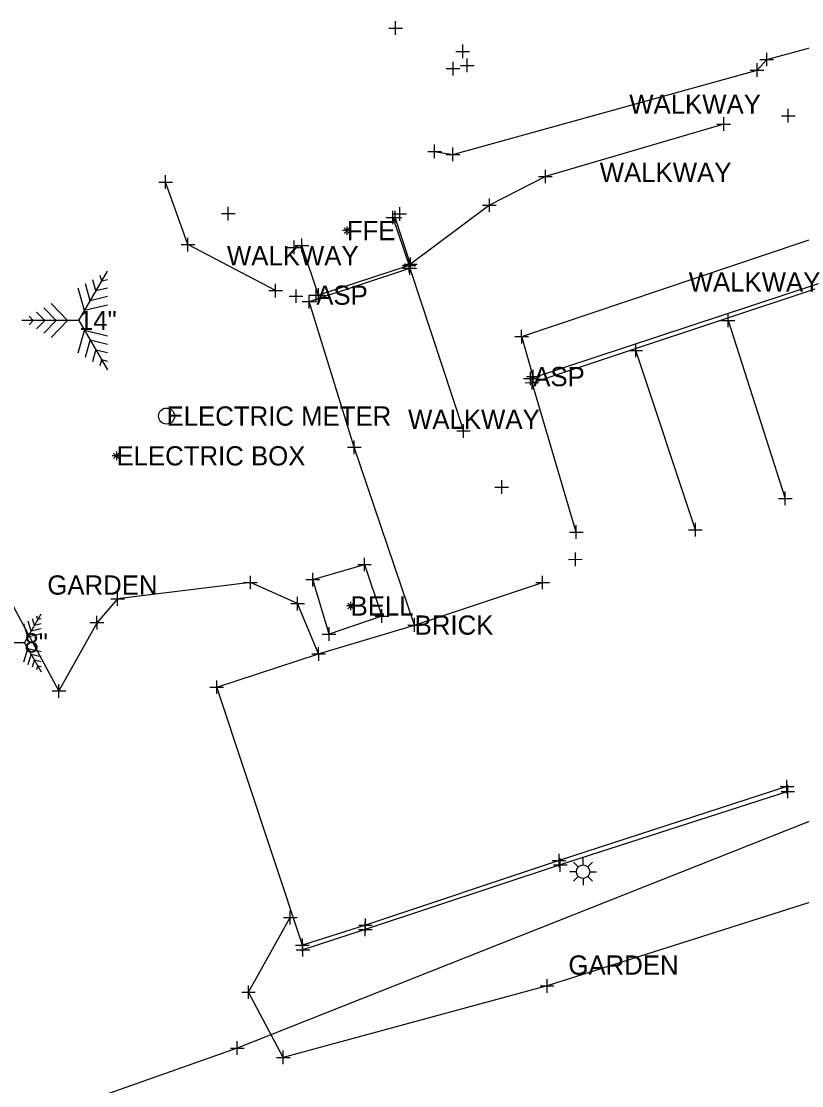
# Model space of a CAD drawing. Extents: x 1729655 to 1739338, y 463812 to 469501.
# Drawn here: x 1734912.1 to 1734985, y 466865.3 to 466964.8 of the extents above; entities that cross this region are included whole.
import ezdxf

# ---------------------------------------------------------------- set-up
doc = ezdxf.new("R2010")
doc.units = 0
for name, color, linetype in [('S_Bridge_Column_Round', 7, 'Continuous'), ('S_Bridge_Deck', 7, 'Continuous'), ('S_Bridge_Parapet', 7, 'Continuous'), ('S_Buildings_Steps', 7, 'Continuous'), ('S_Drainage_Invert_Culvert', 7, 'Continuous'), ('S_Fencing_ChainLink', 7, 'Continuous'), ('S_Fencing_Other', 7, 'Continuous'), ('S_Ground_SpotElevation', 7, 'Continuous'), ('S_Property_Garden', 7, 'Continuous'), ('S_Roadway_Drive_Gravel', 7, 'Continuous'), ('S_Roadway_Sidewalks', 7, 'Continuous'), ('S_Terrain_High_Points', 7, 'Continuous'), ('S_Utilities_Pole_StreetLight', 7, 'Continuous'), ('S_Utilities_UG_Sanitary_MH', 7, 'Continuous')]:
    doc.layers.add(name, color=color, linetype=linetype)

msp = doc.modelspace()

# ---------------------------------------------------------------- linework, layer by layer
at = {"layer": 'S_Bridge_Column_Round'}
for p, q in [((1734946.419, 466964.211), (1734947.691, 466964.213)), ((1734947.056, 466963.576), (1734947.054, 466964.848)), ((1734947.055, 466964.212), (1734947.055, 466964.212)), ((1734953.322, 466961.394), (1734953.32, 466962.666)), ((1734952.685, 466962.029), (1734953.957, 466962.031)), ((1734953.321, 466962.03), (1734953.321, 466962.03)), ((1734953.745, 466960.092), (1734953.743, 466961.364)), ((1734981.087, 466961.276), (1734982.359, 466961.278)), ((1734981.087, 466961.276), (1734982.359, 466961.278)), ((1734981.724, 466960.641), (1734981.722, 466961.913)), ((1734981.724, 466960.641), (1734981.722, 466961.913)), ((1734981.723, 466961.277), (1734981.723, 466961.277)), ((1734981.723, 466961.277), (1734981.723, 466961.277)), ((1734951.79, 466960.426), (1734953.062, 466960.428)), ((1734952.427, 466959.791), (1734952.425, 466961.063)), ((1734952.426, 466960.427), (1734952.426, 466960.427)), ((1734953.108, 466960.727), (1734954.38, 466960.729)), ((1734953.744, 466960.728), (1734953.744, 466960.728)), ((1734980.19, 466960.285), (1734981.462, 466960.287)), ((1734980.827, 466959.65), (1734980.825, 466960.922)), ((1734980.826, 466960.286), (1734980.826, 466960.286)), ((1734983.745, 466955.388), (1734983.743, 466956.66)), ((1734977.079, 466955.237), (1734978.351, 466955.239)), ((1734977.716, 466954.602), (1734977.714, 466955.874)), ((1734977.715, 466955.238), (1734977.715, 466955.238)), ((1734983.108, 466956.023), (1734984.38, 466956.025)), ((1734983.744, 466956.024), (1734983.744, 466956.024)), ((1734950.695, 466952.046), (1734950.693, 466953.318)), ((1734950.695, 466952.046), (1734950.693, 466953.318)), ((1734950.058, 466952.681), (1734951.33, 466952.683)), ((1734950.058, 466952.681), (1734951.33, 466952.683)), ((1734950.694, 466952.682), (1734950.694, 466952.682)), ((1734950.694, 466952.682), (1734950.694, 466952.682)), ((1734951.77, 466952.4), (1734953.042, 466952.402)), ((1734952.407, 466951.765), (1734952.405, 466953.037)), ((1734952.406, 466952.401), (1734952.406, 466952.401)), ((1734925.557, 466949.184), (1734925.555, 466950.456)), ((1734960.407, 466950.337), (1734961.679, 466950.339)), ((1734961.044, 466949.702), (1734961.042, 466950.974)), ((1734961.043, 466950.338), (1734961.043, 466950.338)), ((1734924.92, 466949.819), (1734926.192, 466949.821)), ((1734925.556, 466949.82), (1734925.556, 466949.82)), ((1734955.822, 466947.021), (1734955.82, 466948.293)), ((1734931.419, 466946.236), (1734931.417, 466947.508)), ((1734947.449, 466946.201), (1734947.447, 466947.473)), ((1734955.185, 466947.656), (1734956.457, 466947.658)), ((1734955.821, 466947.657), (1734955.821, 466947.657)), ((1734930.782, 466946.871), (1734932.054, 466946.873)), ((1734931.418, 466946.872), (1734931.418, 466946.872)), ((1734946.161, 466946.504), (1734947.433, 466946.506)), ((1734946.367, 466946.49), (1734947.639, 466946.492)), ((1734946.798, 466945.869), (1734946.796, 466947.141)), ((1734946.797, 466946.505), (1734946.797, 466946.505)), ((1734946.812, 466946.836), (1734948.084, 466946.838)), ((1734947.004, 466945.855), (1734947.002, 466947.127)), ((1734947.003, 466946.491), (1734947.003, 466946.491)), ((1734947.448, 466946.837), (1734947.448, 466946.837)), ((1734927.648, 466943.332), (1734927.646, 466944.604)), ((1734937.57, 466943.076), (1734937.568, 466944.348)), ((1734938.299, 466943.266), (1734938.297, 466944.538)), ((1734927.011, 466943.967), (1734928.283, 466943.969)), ((1734927.647, 466943.968), (1734927.647, 466943.968)), ((1734936.933, 466943.711), (1734938.205, 466943.713)), ((1734937.569, 466943.712), (1734937.569, 466943.712)), ((1734937.662, 466943.901), (1734938.934, 466943.903)), ((1734938.298, 466943.902), (1734938.298, 466943.902)), ((1734948.306, 466941.379), (1734948.304, 466942.651)), ((1734948.371, 466941.135), (1734948.369, 466942.407)), ((1734948.442, 466941.495), (1734948.44, 466942.767)), ((1734947.669, 466942.014), (1734948.941, 466942.016)), ((1734947.734, 466941.77), (1734949.006, 466941.772)), ((1734947.805, 466942.13), (1734949.077, 466942.132)), ((1734948.305, 466942.015), (1734948.305, 466942.015)), ((1734948.37, 466941.771), (1734948.37, 466941.771)), ((1734948.441, 466942.131), (1734948.441, 466942.131)), ((1734935.84, 466939.036), (1734935.838, 466940.308)), ((1734935.203, 466939.671), (1734936.475, 466939.673)), ((1734935.839, 466939.672), (1734935.839, 466939.672)), ((1734937.75, 466938.519), (1734937.748, 466939.791)), ((1734938.967, 466938.007), (1734938.965, 466939.279)), ((1734939.002, 466939.246), (1734940.274, 466939.248)), ((1734939.002, 466939.246), (1734940.274, 466939.248)), ((1734939.222, 466939.249), (1734940.494, 466939.251)), ((1734939.639, 466938.611), (1734939.637, 466939.883)), ((1734939.639, 466938.611), (1734939.637, 466939.883)), ((1734939.638, 466939.247), (1734939.638, 466939.247)), ((1734939.638, 466939.247), (1734939.638, 466939.247)), ((1734939.859, 466938.614), (1734939.857, 466939.886)), ((1734939.858, 466939.25), (1734939.858, 466939.25)), ((1734937.113, 466939.154), (1734938.385, 466939.156)), ((1734937.749, 466939.155), (1734937.749, 466939.155)), ((1734938.33, 466938.642), (1734939.602, 466938.644)), ((1734938.966, 466938.643), (1734938.966, 466938.643)), ((1734978.117, 466936.252), (1734978.115, 466937.524)), ((1734977.48, 466936.887), (1734978.752, 466936.889)), ((1734978.116, 466936.888), (1734978.116, 466936.888)), ((1734958.194, 466935.373), (1734959.466, 466935.375)), ((1734958.831, 466934.738), (1734958.829, 466936.01)), ((1734958.83, 466935.374), (1734958.83, 466935.374)), ((1734969.484, 466933.438), (1734969.482, 466934.71)), ((1734968.847, 466934.073), (1734970.119, 466934.075)), ((1734969.483, 466934.074), (1734969.483, 466934.074)), ((1734959.911, 466930.999), (1734959.909, 466932.271)), ((1734959.007, 466931.457), (1734960.279, 466931.459)), ((1734959.274, 466931.634), (1734960.546, 466931.636)), ((1734959.644, 466930.822), (1734959.642, 466932.094)), ((1734959.643, 466931.458), (1734959.643, 466931.458)), ((1734959.799, 466930.43), (1734959.797, 466931.702)), ((1734959.91, 466931.635), (1734959.91, 466931.635)), ((1734959.162, 466931.065), (1734960.434, 466931.067)), ((1734959.798, 466931.066), (1734959.798, 466931.066)), ((1734952.76, 466926.551), (1734954.032, 466926.553)), ((1734953.397, 466925.916), (1734953.395, 466927.188)), ((1734953.396, 466926.552), (1734953.396, 466926.552)), ((1734943.193, 466924.389), (1734943.191, 466925.661)), ((1734942.556, 466925.024), (1734943.828, 466925.026)), ((1734943.192, 466925.025), (1734943.192, 466925.025)), ((1734956.963, 466920.673), (1734956.961, 466921.945)), ((1734956.326, 466921.308), (1734957.598, 466921.31)), ((1734956.962, 466921.309), (1734956.962, 466921.309)), ((1734983.462, 466919.608), (1734983.46, 466920.88)), ((1734982.825, 466920.243), (1734984.097, 466920.245)), ((1734983.461, 466920.244), (1734983.461, 466920.244)), ((1734963.929, 466916.464), (1734963.927, 466917.736)), ((1734963.929, 466916.464), (1734963.927, 466917.736)), ((1734975.063, 466916.68), (1734975.061, 466917.952)), ((1734963.292, 466917.099), (1734964.564, 466917.101)), ((1734963.292, 466917.099), (1734964.564, 466917.101)), ((1734963.928, 466917.1), (1734963.928, 466917.1)), ((1734963.928, 466917.1), (1734963.928, 466917.1)), ((1734974.426, 466917.315), (1734975.698, 466917.317)), ((1734975.062, 466917.316), (1734975.062, 466917.316)), ((1734944.144, 466913.432), (1734944.142, 466914.704)), ((1734963.218, 466914.551), (1734964.49, 466914.553)), ((1734963.855, 466913.916), (1734963.853, 466915.188)), ((1734963.854, 466914.552), (1734963.854, 466914.552)), ((1734943.507, 466914.067), (1734944.779, 466914.069)), ((1734944.143, 466914.068), (1734944.143, 466914.068)), ((1734932.85, 466912.387), (1734934.122, 466912.389)), ((1734933.487, 466911.752), (1734933.485, 466913.024)), ((1734933.486, 466912.388), (1734933.486, 466912.388)), ((1734938.669, 466912.662), (1734939.941, 466912.664)), ((1734939.306, 466912.027), (1734939.304, 466913.299)), ((1734939.305, 466912.663), (1734939.305, 466912.663)), ((1734960.147, 466912.384), (1734961.419, 466912.386)), ((1734960.784, 466911.749), (1734960.782, 466913.021)), ((1734960.783, 466912.385), (1734960.783, 466912.385)), ((1734921.074, 466910.214), (1734921.072, 466911.486)), ((1734920.437, 466910.849), (1734921.709, 466910.851)), ((1734921.073, 466910.85), (1734921.073, 466910.85)), ((1734937.254, 466910.408), (1734938.526, 466910.41)), ((1734937.891, 466909.773), (1734937.889, 466911.045)), ((1734937.89, 466910.409), (1734937.89, 466910.409)), ((1734945.77, 466908.615), (1734945.768, 466909.887)), ((1734918.514, 466908.642), (1734919.786, 466908.644)), ((1734919.151, 466908.007), (1734919.149, 466909.279)), ((1734919.15, 466908.643), (1734919.15, 466908.643)), ((1734945.133, 466909.25), (1734946.405, 466909.252)), ((1734945.769, 466909.251), (1734945.769, 466909.251)), ((1734948.193, 466908.405), (1734949.465, 466908.407)), ((1734948.193, 466908.405), (1734949.465, 466908.407)), ((1734948.83, 466907.77), (1734948.828, 466909.042)), ((1734948.83, 466907.77), (1734948.828, 466909.042)), ((1734948.829, 466908.406), (1734948.829, 466908.406)), ((1734948.829, 466908.406), (1734948.829, 466908.406)), ((1734940.2, 466907.56), (1734941.472, 466907.562)), ((1734940.837, 466906.925), (1734940.835, 466908.197)), ((1734940.836, 466907.561), (1734940.836, 466907.561)), ((1734939.225, 466905.707), (1734940.497, 466905.709)), ((1734939.225, 466905.707), (1734940.497, 466905.709)), ((1734939.862, 466905.072), (1734939.86, 466906.344)), ((1734939.862, 466905.072), (1734939.86, 466906.344)), ((1734939.861, 466905.708), (1734939.861, 466905.708)), ((1734939.861, 466905.708), (1734939.861, 466905.708)), ((1734915.597, 466901.61), (1734915.595, 466902.882)), ((1734929.704, 466902.602), (1734930.976, 466902.604)), ((1734930.341, 466901.967), (1734930.339, 466903.239)), ((1734930.34, 466902.603), (1734930.34, 466902.603)), ((1734914.96, 466902.245), (1734916.232, 466902.247)), ((1734915.596, 466902.246), (1734915.596, 466902.246)), ((1734983.619, 466892.677), (1734983.617, 466893.949)), ((1734983.703, 466892.216), (1734983.701, 466893.488)), ((1734982.982, 466893.312), (1734984.254, 466893.314)), ((1734983.066, 466892.851), (1734984.338, 466892.853)), ((1734983.618, 466893.313), (1734983.618, 466893.313)), ((1734983.702, 466892.852), (1734983.702, 466892.852)), ((1734962.326, 466885.765), (1734962.324, 466887.037)), ((1734962.436, 466885.344), (1734962.434, 466886.616)), ((1734961.689, 466886.4), (1734962.961, 466886.402)), ((1734961.799, 466885.979), (1734963.071, 466885.981)), ((1734962.325, 466886.401), (1734962.325, 466886.401)), ((1734962.435, 466885.98), (1734962.435, 466885.98)), ((1734937.206, 466880.424), (1734937.204, 466881.696)), ((1734936.569, 466881.059), (1734937.841, 466881.061)), ((1734937.205, 466881.06), (1734937.205, 466881.06)), ((1734944.219, 466879.324), (1734944.217, 466880.596)), ((1734944.241, 466879.707), (1734944.239, 466880.979)), ((1734943.582, 466879.959), (1734944.854, 466879.961)), ((1734943.604, 466880.342), (1734944.876, 466880.344)), ((1734944.218, 466879.96), (1734944.218, 466879.96)), ((1734944.24, 466880.343), (1734944.24, 466880.343)), ((1734938.343, 466877.845), (1734938.341, 466879.117)), ((1734938.39, 466877.416), (1734938.388, 466878.688)), ((1734937.706, 466878.48), (1734938.978, 466878.482)), ((1734937.753, 466878.051), (1734939.025, 466878.053)), ((1734938.342, 466878.481), (1734938.342, 466878.481)), ((1734938.389, 466878.052), (1734938.389, 466878.052)), ((1734933.305, 466873.454), (1734933.303, 466874.726)), ((1734960.572, 466874.674), (1734961.844, 466874.676)), ((1734961.209, 466874.039), (1734961.207, 466875.311)), ((1734961.208, 466874.675), (1734961.208, 466874.675)), ((1734932.668, 466874.089), (1734933.94, 466874.091)), ((1734933.304, 466874.09), (1734933.304, 466874.09)), ((1734931.616, 466868.867), (1734932.888, 466868.869)), ((1734932.254, 466868.232), (1734932.251, 466869.504)), ((1734932.252, 466868.868), (1734932.252, 466868.868)), ((1734936.557, 466867.358), (1734936.555, 466868.63)), ((1734935.92, 466867.993), (1734937.192, 466867.995)), ((1734936.556, 466867.994), (1734936.556, 466867.994))]:
    msp.add_line(p, q, dxfattribs=at)
at = {"layer": 'S_Bridge_Deck'}
for p, q in [((1734964.563, 466885.979), (1734964.563, 466886.603)), ((1734964.122, 466885.796), (1734963.681, 466886.237)), ((1734965.004, 466885.796), (1734965.445, 466886.237)), ((1734963.939, 466885.355), (1734963.315, 466885.355)), ((1734964.122, 466884.914), (1734963.681, 466884.473)), ((1734964.563, 466884.731), (1734964.563, 466884.107)), ((1734965.004, 466884.914), (1734965.445, 466884.473)), ((1734965.187, 466885.355), (1734965.811, 466885.355))]:
    msp.add_line(p, q, dxfattribs=at)
msp.add_circle((1734964.563, 466885.355), 0.624, dxfattribs=at)
at = {"layer": 'S_Bridge_Parapet'}
for p, q in [((1734917.46, 466936.875), (1734920.123, 466941.486)), ((1734918.526, 466938.719), (1734918.069, 466940.298)), ((1734919.055, 466939.639), (1734918.754, 466940.695)), ((1734919.589, 466940.563), (1734919.439, 466941.092)), ((1734920.123, 466940.695), (1734919.589, 466940.563)), ((1734917.992, 466937.798), (1734917.385, 466939.904)), ((1734920.123, 466939.904), (1734919.055, 466939.639)), ((1734916.394, 466936.875), (1734914.874, 466938.457)), ((1734920.123, 466938.322), (1734917.992, 466937.798)), ((1734920.123, 466939.116), (1734918.526, 466938.719)), ((1734913.199, 466936.875), (1734912.821, 466937.269)), ((1734914.265, 466936.875), (1734913.505, 466937.663)), ((1734915.331, 466936.875), (1734914.19, 466938.06)), ((1734917.46, 466936.875), (1734912.136, 466936.875)), ((1734912.821, 466936.481), (1734913.199, 466936.875)), ((1734913.505, 466936.084), (1734914.265, 466936.875)), ((1734914.19, 466935.687), (1734915.331, 466936.875)), ((1734914.874, 466935.293), (1734916.394, 466936.875)), ((1734917.46, 466936.875), (1734920.123, 466932.264)), ((1734917.385, 466933.846), (1734917.992, 466935.952)), ((1734920.123, 466935.425), (1734917.992, 466935.952)), ((1734918.069, 466933.449), (1734918.526, 466935.029)), ((1734920.123, 466934.634), (1734918.526, 466935.029)), ((1734918.754, 466933.052), (1734919.055, 466934.108)), ((1734920.123, 466933.846), (1734919.055, 466934.108)), ((1734919.439, 466932.658), (1734919.589, 466933.187)), ((1734920.123, 466933.052), (1734919.589, 466933.187))]:
    msp.add_line(p, q, dxfattribs=at)
at = {"layer": 'S_Buildings_Steps'}
for p, q in [((1734942.885, 466945.284), (1734942.099, 466945.284)), ((1734942.754, 466945.022), (1734942.23, 466945.546)), ((1734942.754, 466945.546), (1734942.23, 466945.022)), ((1734942.492, 466945.677), (1734942.492, 466944.891)), ((1734921.23, 466923.965), (1734920.706, 466924.489)), ((1734921.23, 466924.489), (1734920.706, 466923.965)), ((1734920.968, 466924.62), (1734920.968, 466923.834)), ((1734921.361, 466924.227), (1734920.575, 466924.227)), ((1734943.106, 466909.931), (1734942.582, 466910.455)), ((1734943.106, 466910.455), (1734942.582, 466909.931)), ((1734942.844, 466910.586), (1734942.844, 466909.8)), ((1734943.237, 466910.193), (1734942.451, 466910.193))]:
    msp.add_line(p, q, dxfattribs=at)
at = {"layer": 'S_Drainage_Invert_Culvert'}
for points in [[(1734939.861, 466905.708), (1734937.89, 466910.409), (1734933.486, 466912.388), (1734921.073, 466910.85), (1734919.15, 466908.643), (1734915.596, 466902.246), (1734911.38, 466910.072), (1734910.817, 466913.717), (1734893.9, 466918.589), (1734888.393, 466923.539)], [(1735001.99, 466881.916), (1734992.895, 466884.759), (1734961.208, 466874.675), (1734936.556, 466867.994), (1734933.304, 466874.09), (1734937.205, 466881.06)]]:
    msp.add_lwpolyline(points, dxfattribs=at)
at = {"layer": 'S_Fencing_ChainLink'}
for p, q in [((1734912.37, 466906.744), (1734913.94, 466909.46)), ((1734912.684, 466907.287), (1734912.328, 466908.531)), ((1734912.998, 466907.83), (1734912.731, 466908.764)), ((1734913.312, 466908.374), (1734913.134, 466908.997)), ((1734913.94, 466908.531), (1734913.312, 466908.374)), ((1734913.626, 466908.917), (1734913.537, 466909.229)), ((1734913.94, 466908.997), (1734913.626, 466908.917)), ((1734913.94, 466907.599), (1734912.684, 466907.287)), ((1734913.94, 466908.064), (1734912.998, 466907.83)), ((1734912.37, 466906.744), (1734909.234, 466906.744)), ((1734912.37, 466906.744), (1734913.94, 466904.028)), ((1734912.328, 466904.962), (1734912.684, 466906.201)), ((1734913.94, 466905.891), (1734912.684, 466906.201)), ((1734912.731, 466904.728), (1734912.998, 466905.658)), ((1734913.94, 466905.426), (1734912.998, 466905.658)), ((1734913.134, 466904.495), (1734913.312, 466905.114)), ((1734913.94, 466904.962), (1734913.312, 466905.114)), ((1734913.537, 466904.262), (1734913.626, 466904.571)), ((1734913.94, 466904.495), (1734913.626, 466904.571))]:
    msp.add_line(p, q, dxfattribs=at)
at = {"layer": 'S_Fencing_Other'}
msp.add_circle((1734925.647, 466927.948), 0.749, dxfattribs=at)
at = {"layer": 'S_Ground_SpotElevation'}
for p, q in [((1734959.798, 466931.066), (1734986.247, 466939.835)), ((1734963.928, 466917.1), (1734959.798, 466931.066)), ((1734948.829, 466908.406), (1734960.783, 466912.385)), ((1734939.861, 466905.708), (1734948.829, 466908.406)), ((1734930.34, 466902.603), (1734939.861, 466905.708)), ((1734938.342, 466878.481), (1734930.34, 466902.603)), ((1734983.618, 466893.313), (1734962.325, 466886.401)), ((1734962.325, 466886.401), (1734944.24, 466880.343)), ((1734944.24, 466880.343), (1734938.342, 466878.481))]:
    msp.add_line(p, q, dxfattribs=at)
at = {"layer": 'S_Property_Garden'}
for p, q in [((1734977.715, 466955.238), (1734961.043, 466950.338)), ((1734961.043, 466950.338), (1734955.821, 466947.657)), ((1734927.647, 466943.968), (1734925.556, 466949.82)), ((1734955.821, 466947.657), (1734948.441, 466942.131)), ((1734948.441, 466942.131), (1734947.003, 466946.491)), ((1734935.839, 466939.672), (1734927.647, 466943.968)), ((1734938.966, 466938.643), (1734948.37, 466941.771)), ((1734948.37, 466941.771), (1734953.396, 466926.552)), ((1734943.192, 466925.025), (1734938.966, 466938.643)), ((1734948.829, 466908.406), (1734943.192, 466925.025))]:
    msp.add_line(p, q, dxfattribs=at)
for points in [[(1734950.694, 466952.682), (1734952.406, 466952.401), (1734980.826, 466960.286), (1734981.723, 466961.277), (1734986.77, 466962.646)], [(1734959.91, 466931.635), (1734958.83, 466935.374), (1734991.61, 466946.425), (1734991.018, 466948.204)]]:
    msp.add_lwpolyline(points, dxfattribs=at)
at = {"layer": 'S_Roadway_Drive_Gravel'}
for points in [[(1734978.116, 466936.888), (1734983.461, 466920.244)], [(1734975.062, 466917.316), (1734969.483, 466934.074)]]:
    msp.add_lwpolyline(points, dxfattribs=at)
at = {"layer": 'S_Roadway_Sidewalks'}
msp.add_lwpolyline([(1734946.797, 466946.505), (1734948.305, 466942.015), (1734939.858, 466939.25), (1734938.298, 466943.902)], dxfattribs=at)
msp.add_lwpolyline([(1734940.836, 466907.561), (1734939.305, 466912.663), (1734944.143, 466914.068), (1734945.769, 466909.251)], close=True, dxfattribs=at)
at = {"layer": 'S_Utilities_Pole_StreetLight'}
msp.add_lwpolyline([(1735055.655, 466913.549), (1734995.118, 466893.793), (1734932.252, 466868.868), (1734850.4, 466839.95)], dxfattribs=at)
at = {"layer": 'S_Utilities_UG_Sanitary_MH'}
for p, q in [((1734959.643, 466931.458), (1734986.566, 466940.34)), ((1734983.702, 466892.852), (1734962.435, 466885.98)), ((1734962.435, 466885.98), (1734944.218, 466879.96)), ((1734944.218, 466879.96), (1734938.389, 466878.052))]:
    msp.add_line(p, q, dxfattribs=at)

# ---------------------------------------------------------------- texts
at = {"layer": 'S_Terrain_High_Points'}
for s, p in [('WALKWAY', (1734968.88, 466956.203)), ('WALKWAY', (1734966.126, 466949.828)), ('FFE', (1734942.492, 466944.384)), ('WALKWAY', (1734931.292, 466942.035)), ('WALKWAY', (1734974.438, 466939.584)), ('ASP', (1734939.638, 466938.347)), ('ASP', (1734939.638, 466938.347)), ('14"', (1734917.46, 466935.975)), ('ASP', (1734959.91, 466930.735)), ('ELECTRIC METER', (1734925.647, 466927.048)), ('WALKWAY', (1734948.214, 466926.746)), ('ELECTRIC BOX', (1734920.968, 466923.327)), ('GARDEN', (1734914.507, 466911.251)), ('BELL', (1734942.844, 466909.293)), ('BRICK', (1734948.829, 466907.506)), ('BRICK', (1734948.829, 466907.506)), ('8"', (1734912.37, 466905.844)), ('GARDEN', (1734963.196, 466875.727))]:
    msp.add_text(s, height=1.8, dxfattribs=at).set_placement(p)

doc.saveas('drawing.dxf')
